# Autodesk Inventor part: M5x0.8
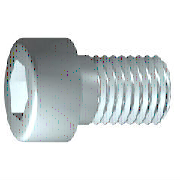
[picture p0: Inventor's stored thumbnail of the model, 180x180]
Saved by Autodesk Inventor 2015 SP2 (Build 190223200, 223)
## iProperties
IsCustomPart: 0
Manager: KYOUNG IL JANG
Company: 한국ATC센터
Created: 2009-02
Part Number: M5x0.8
Material: Steel, Mild
Description: 6각머리 태핑 나사
Document SubType Name: Modeling
Standard: KS B 1003
Standards Organization: KS
Language: ko-KR
Size Designation: M 5 x 20
Categories: <MemberInstance><Categories><Category DisplayName="조임쇠" InternalName="e4da775c-781d-43d5-af7c-5136215cf5a6" Mnemonic="FSTN"><Category DisplayName="볼트" InternalN
Density: 1 g/cm^3
Checked By: KYOUNG IL JANG
Vendor: CBT Solutions
Designer: KYOUNG IL JANG
Appearance: Metal-Steel
Author: KYOUNG IL JANG
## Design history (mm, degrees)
sketch "스케치1"
  geometry: L1 (-1.167, 0)-(20, 0); L2 (20, 0)-(20, 2.5); L3 (20, 2.5)-(2, 2.5); L4 (2, 2.5)-(1.509, 2.5); L5 (1.509, 2.5)-(0, 2.5); L6 (0, 2.5)-(0, 4.25); L7 (0, 4.25)-(-5, 4.25); L8 (-5, 4.25)-(-5, 2.309); L9 (-5, 2.309)-(-2.5, 2.309); L10 (-2.5, 2.309)-(-1.167, 0); L11 (-10, 0)-(25, 0) reference; L12 (0, -0.85)-(0, 5.1) reference; L13 (2, 2.5)-(0, 2.5)
  constraints: 22 end point, 6 parallel, 2 collinear, 2 perpendicular, 1 horizontal, 1 point on line
  dimensions: "d1" = 18 distance from line of L3.end L2 (= GEL); "d2" = 0.49086 distance of L4.end L3.end (computed from GAL); "d3" = 5 distance between parallel lines of L8 L6 (= KOH); "d4" = 2.5 distance of L8.end L9.end (= INTI); "d5" = 60 deg angle of L10 L1; "d6" = 5 diameter of L3 L1 (= GD); "d7" = 5 diameter of L5 L1 (= BDM); "d8" = 4.6188 diameter of L9 L1 (= 1.1547 x SW); "d9" = 8.5 diameter of L7 L1 (= KOD); "d26" = 20 distance between parallel lines of L12 L2 (= NLG)
revolve "본체" sketch "스케치1" stored, may be unused: angle "d10" = 90 deg
sketch "스케치2"
  geometry: L1 (0, -5.95)-(0, 5.95) reference; L2 (-5.95, 0)-(5.95, 0) reference; L3 (2.309, 0)-(1.155, -2); L4 (1.155, -2)-(-1.155, -2); L5 (-1.155, -2)-(-2.309, 0); L6 (-2.309, 0)-(-1.155, 2); L7 (-1.155, 2)-(1.155, 2); L8 (1.155, 2)-(2.309, 0); 2 further points
  constraints: 12 end point, 1 coincident, 1 horizontal alignment, 1 point on line, 12 other
extrude "슬롯" join sketch "스케치2" stored distance "d11" = 10; taper "d12" = 0 deg
workplane "Work Plane1"
fillet "Fillet2" dims "d30" = 0.1 (= R)
body "Solid1"
fillet "모깎기1" dims "d17" = 0.5 (= RR)
feature "스레드" dims "d13" = 18 (= GEL), "d14" = 0
chamfer "모따기1" distance "d15" = 0.49076 (= -0.5 x SPD + 0.5 x GD); stored, may be unused: second distance "d16" = 0.49076 (= GUL), angle "d27" = 45 deg
other parameters: "GD" = 5 (= NND) [user parameter; used in 2 equation terms], "NLG" = 20 [user parameter; used in 1 equation term], "GEL" = 18 [user parameter; used in 2 equation terms], "KOD" = 8.5 [user parameter; used in 1 equation term], "KOH" = 5 [user parameter; used in 1 equation term], "INTI" = 2.5 [user parameter; used in 1 equation term], "GAL" = 0.49076 (= 0.61345 x PTC) [user parameter; used in 1 equation term], "GUL" = 0.49076 (= 0.61345 x PTC) [user parameter; used in 1 equation term], "BDM" = 5 (= NND) [user parameter; used in 1 equation term], "SW" = 4 [user parameter; used in 2 equation terms], "RR" = 0.5 [user parameter; used in 1 equation term], "SPD" = 4.01848 (= NND - 1.2269 x PTC) [user parameter; used in 1 equation term], "d19" = 0, "d28" = 0, "d29" = 0, "R" = 0.1 [user parameter; used in 1 equation term], "PHH" = 0.2 [user parameter], "GD1" = 4.01848 (= THREADDIA - 1.2269 x PTC) [user parameter], "THREADDIA" = 5 [user parameter; used in 1 equation term], "FAWI" = 45 deg [user parameter], "TPU" = 12.5 (computed from PTC) [user parameter], "PTC" = 0.8 [user parameter; used in 5 equation terms], "NND" = 5 [user parameter; used in 3 equation terms], "TOA" = 30 deg [user parameter], "E0" = 4.62 (= 1.155 x SW) [user parameter]
